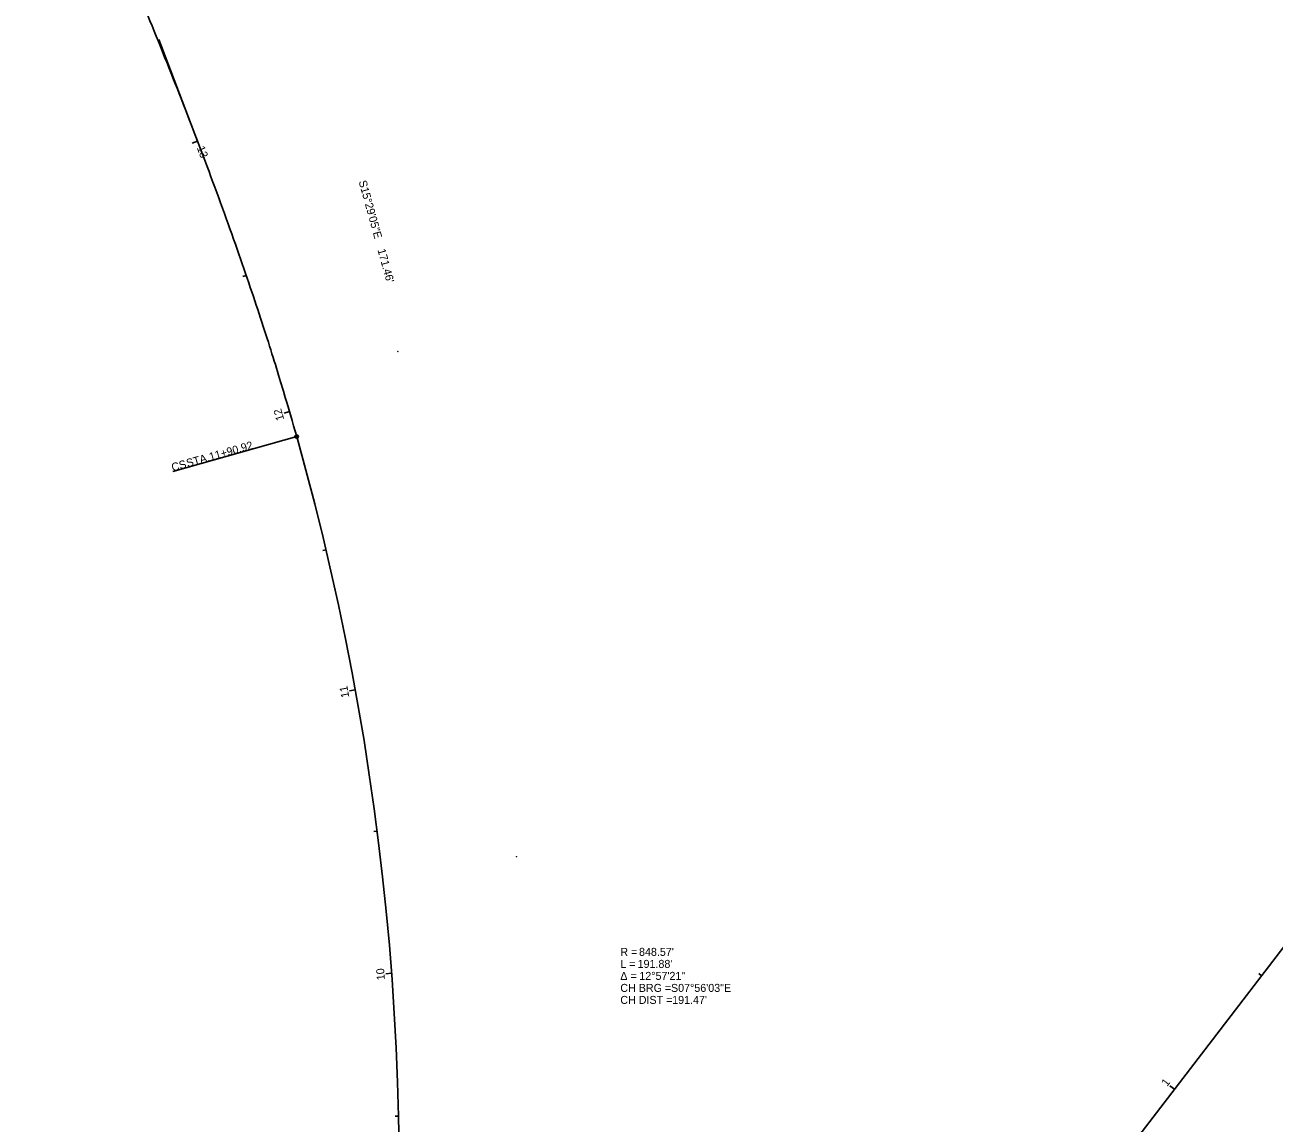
# Model space of a CAD drawing. Extents: x 1609531 to 1610891, y 471231 to 473177.
# Drawn here: x 1609986.3 to 1610423.2, y 472290.7 to 472674.7 of the extents above; entities that cross this region are included whole.
import ezdxf

# ---------------------------------------------------------------- set-up
doc = ezdxf.new("R2010")
doc.units = 0
for name, color, linetype in [('Default', 7, 'Continuous'), ('PV_X_Shoulder_Aggregate', 7, 'Continuous'), ('RD_X_GR_Rt', 7, 'Continuous'), ('SV_P_Mon_Cells_Set', 7, 'Continuous'), ('SV_X_Control_Cells_Found', 7, 'Continuous'), ('UT_X_Misc_Cells', 7, 'Continuous'), ('UT_X_Water', 7, 'Continuous')]:
    doc.layers.add(name, color=color, linetype=linetype)

msp = doc.modelspace()

# ---------------------------------------------------------------- linework, layer by layer
at = {"layer": 'Default'}
msp.add_arc((1609162.3, 472271.47), 954.93, 329.64417, 15.75667, dxfattribs=at)
msp.add_open_spline([(1610081.35, 472530.78), (1610079.94, 472535.8), (1610077.03, 472545.8), (1610070.9, 472565.71), (1610062.71, 472590.43), (1610052.15, 472619.85), (1610041, 472649.04), (1610029.36, 472678.05), (1610017.38, 472706.91), (1610007.19, 472730.87), (1609998.99, 472750.02), (1609994.87, 472759.59), (1609992.82, 472764.38)], degree=3, dxfattribs=at)
at = {"layer": 'PV_X_Shoulder_Aggregate'}
for p, q in [((1610046.66, 472634.16), (1610044.79, 472633.45)), ((1610063.7, 472587.16), (1610062.56, 472586.77)), ((1610078.85, 472539.51), (1610076.93, 472538.95)), ((1610091.62, 472491.17), (1610090.45, 472490.9)), ((1610101.84, 472442.24), (1610099.87, 472441.88)), ((1610109.49, 472392.83), (1610108.3, 472392.68)), ((1610114.55, 472343.09), (1610112.55, 472342.94)), ((1610418.81, 472342.22), (1610417.86, 472342.95)), ((1610388.38, 472302.54), (1610386.79, 472303.76)), ((1610116.99, 472293.16), (1610115.79, 472293.13))]:
    msp.add_line(p, q, dxfattribs=at)
at = {"layer": 'RD_X_GR_Rt'}
msp.add_line((1610046.66, 472634.16), (1610033.11, 472669.69), dxfattribs=at)
at = {"layer": 'SV_P_Mon_Cells_Set'}
for centre in [(1610116.78, 472560.56), (1610116.78, 472560.56), (1610158.24, 472383.87), (1610158.24, 472383.87)]:
    msp.add_circle(centre, 0.05, dxfattribs=at)
at = {"layer": 'SV_X_Control_Cells_Found'}
msp.add_line((1610081.35, 472530.78), (1610038.04, 472518.56), dxfattribs=at)
msp.add_circle((1610081.35, 472530.78), 0.6, dxfattribs=at)
at = {"layer": 'UT_X_Misc_Cells'}
msp.add_line((1610327.51, 472223.2), (1610631.82, 472619.93), dxfattribs=at)
msp.add_arc((1609162.3, 472271.47), 954.93, 329.64417, 15.75667, dxfattribs=at)
msp.add_open_spline([(1610081.35, 472530.78), (1610079.94, 472535.8), (1610077.03, 472545.8), (1610070.9, 472565.71), (1610062.71, 472590.43), (1610052.15, 472619.85), (1610041, 472649.04), (1610029.36, 472678.05), (1610017.38, 472706.91), (1610007.19, 472730.87), (1609998.99, 472750.02), (1609994.87, 472759.59), (1609992.82, 472764.38)], degree=3, dxfattribs=at)

# ---------------------------------------------------------------- texts
at = {"layer": 'PV_X_Shoulder_Aggregate'}
for s, rotation, p in [('13', 290.8736, (1610046.37, 472631.82)), ('12', 106.2915, (1610077.03, 472536.8)), ('11', 100.3014, (1610099.76, 472439.72)), ('10', 94.3014, (1610112.21, 472340.76)), ('1', 52.5106, (1610385.79, 472303.28))]:
    msp.add_text(s, height=2.8, rotation=rotation, dxfattribs=at).set_placement(p)
at = {"layer": 'SV_X_Control_Cells_Found'}
for s, p in [('11+90.92', (1610051.16, 472522.3)), ('CS', (1610037.99, 472518.59)), (' STA. ', (1610042.19, 472519.77))]:
    msp.add_text(s, height=2.8, rotation=15.7567, dxfattribs=at).set_placement(p)
at = {"layer": 'UT_X_Water'}
for s, p in [('S15°29\'05"E', (1610103, 472620)), ("171.46'", (1610109.6, 472596.07))]:
    msp.add_text(s, height=2.8, rotation=285.4848, dxfattribs=at).set_placement(p)
for s, p in [('R = ', (1610194.55, 472349.17)), ("848.57'", (1610201.09, 472349.17)), ('L = ', (1610194.55, 472344.97)), ("191.88'", (1610200.59, 472344.97)), ('Δ = ', (1610194.55, 472340.77)), ('12°57\'21"', (1610201.2, 472340.77)), ('CH BRG = ', (1610194.55, 472336.57)), ('S07°56\'03"E', (1610212.27, 472336.57)), ('CH DIST = ', (1610194.55, 472332.37)), ("191.47'", (1610212.69, 472332.37))]:
    msp.add_text(s, height=2.8, dxfattribs=at).set_placement(p)

doc.saveas('drawing.dxf')
